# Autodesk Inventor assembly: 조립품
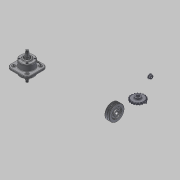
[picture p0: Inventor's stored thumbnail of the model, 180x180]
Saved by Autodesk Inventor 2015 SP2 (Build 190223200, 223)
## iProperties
Created: 2015-07
Part Number: 조립품
Document SubType Name: Assembly
Designer: AMC
Author: AMC
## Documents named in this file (12)
- C:\Users\AMC\Desktop\450735V1007\조립품.iam
- C:\Users\AMC\Desktop\450735V1007\본체.ipt
- C:\Users\AMC\Desktop\450735V1007\2-커버.ipt
- C:\Users\AMC\Desktop\450735V1007\3-축.ipt
- C:\Users\AMC\Desktop\450735V1007\4-V벨트풀리.ipt
- C:\Users\AMC\Desktop\450735V1007\5-체인 스프로킷.ipt
- C:\Users\AMC\Desktop\450735V1007\6-베어링 6206.ipt
- C:\Users\AMC\Desktop\450735V1007\7-부시.ipt
- C:\Users\AMC\Desktop\450735V1007\8-오일실 30x42.ipt
- C:\Users\AMC\Desktop\450735V1007\9-M16-너트.ipt
- C:\Users\AMC\Desktop\450735V1007\10-M6.ipt
- C:\Users\AMC\Desktop\450735V1007\11-키 6x6.ipt
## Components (20 placed, 10 different names)
1. 2-커버:1
2. 3-축:1
3. 4-V벨트풀리:1
4. 5-체인 스프로킷:1
5. 6-베어링 6206:1
6. 7-부시:1
7. 8-8-오일실 30x42:1
8. 9-M16 너트:1
9. 10-M6:1
10. 11-키 6x6:1
11. 2-커버:2
12. 6-베어링 6206:2
13. 8-8-오일실 30x42:2
14. 10-M6:2
15. 10-M6:3
16. 10-M6:4
17. 10-M6:5
18. 10-M6:6
19. 10-M6:7
20. 10-M6:8
